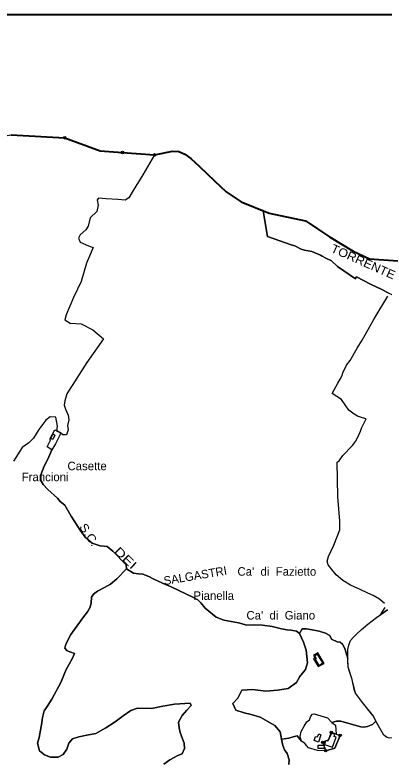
# Model space of a CAD drawing. Extents: x 645880 to 658994, y 884400 to 894744.
# Drawn here: x 656935 to 657672, y 893255 to 894744 of the extents above; entities that cross this region are included whole.
import ezdxf
from ezdxf.enums import TextEntityAlignment as Align

# ---------------------------------------------------------------- set-up
doc = ezdxf.new("R2010")
doc.units = 0
doc.header["$LTSCALE"] = 10
doc.header["$PDMODE"] = 32
doc.header["$PDSIZE"] = 5
for name, color, linetype, lineweight in [('16', 7, 'Continuous', 25), ('17', 7, 'Continuous', 25), ('18', 7, 'Continuous', 25), ('3', 7, 'Continuous', 25), ('4', 7, 'Continuous', 25), ('43', 7, 'Continuous', 25), ('59', 7, 'Continuous', 40), ('62', 7, 'Continuous', 35), ('7', 7, 'Continuous', 25), ('8', 7, 'Continuous', 25)]:
    doc.layers.add(name, color=color, linetype=linetype, lineweight=lineweight)
doc.layers.add('60', color=7, linetype='Continuous')

msp = doc.modelspace()

# ---------------------------------------------------------------- linework, layer by layer
at = {"layer": '16'}
for points in [[(657680.24, 894188.92), (657666.12, 894195.92), (657645.87, 894205.42), (657629.62, 894213.92), (657618.12, 894219.92), (657616.37, 894220.92), (657614.62, 894216.92), (657579.24, 894241.42), (657567.24, 894252.42), (657555.8, 894257.92), (657548.37, 894261.67), (657544.99, 894263.92), (657527.62, 894270.92), (657513.24, 894273.92), (657506.49, 894275.92), (657493.74, 894282.67), (657486.49, 894284.42), (657439.24, 894300.98), (657430.78, 894352.65), (657387.01, 894370.39), (657356.62, 894390.26), (657333.58, 894412.71), (657303.9, 894440.82), (657286.23, 894457.27), (657274.22, 894465.5), (657262.2, 894470.98), (657249.48, 894471.67), (657214.17, 894464.13), (657190.39, 894424.35), (657171.14, 894392.96), (657162.82, 894378.21), (657155.44, 894373.93), (657140.71, 894374.88), (657117.2, 894376.49), (657102.45, 894377.5)], [(657102.45, 894377.5), (657099.36, 894374.4), (657101.73, 894363.47), (657098.63, 894351.34), (657085.32, 894338.26), (657081.52, 894322.08), (657077, 894314.71), (657065.83, 894304.49), (657062.03, 894297.83), (657065.83, 894289.74), (657081.99, 894282.84), (657091.51, 894279.27), (657078.2, 894247.64), (657067.74, 894211.49), (657052.53, 894179.14), (657037.54, 894144.89), (657035.17, 894134.9), (657045.63, 894128.25), (657067.73, 894127.06), (657091.02, 894114.93), (657112.41, 894097.09)], [(657672.88, 893568.11), (657662.51, 893576.7), (657650.21, 893584), (657639.22, 893589.1), (657624.33, 893596.13), (657604.73, 893604.78), (657589.74, 893614.01), (657576.62, 893625.21), (657567.51, 893635.85), (657560.6, 893645.47), (657558.57, 893652.72), (657561.27, 893662.35), (657571.39, 893684.62), (657583.37, 893715.34), (657583.98, 893732.83), (657579.37, 893781.87), (657578.57, 893850.22), (657582.32, 893853.22), (657589.83, 893863.48), (657609.12, 893883.73), (657614.7, 893891.81), (657619.99, 893901.51), (657625.04, 893912.56), (657627.19, 893918.71), (657636.08, 893937.11), (657628.85, 893938.92), (657619.17, 893942.51), (657612.37, 893946.53), (657601.47, 893954.52), (657594.54, 893964.93), (657587.26, 893975.31), (657568.2, 893987.82), (657579.64, 894007.93), (657584.42, 894016.54), (657587.4, 894022.17), (657589.36, 894028.91), (657596.75, 894044.05), (657604.14, 894053.55), (657618.57, 894078.19), (657628.07, 894094.38), (657652.34, 894136.63), (657679.35, 894181.74)], [(657112.41, 894097.09), (657079.13, 894049.76), (657038.73, 893986.97), (657034.69, 893973.18), (657033.5, 893964.62), (657036.12, 893956.05), (657041.82, 893944.4), (657043.07, 893935.18), (657040.6, 893923.66), (657041.42, 893914.88), (657038.13, 893904.74), (657031.28, 893905.28), (657026.77, 893908.54), (657016.62, 893887.42), (657009.04, 893874.78)], [(657019.22, 893912.86), (657020.67, 893922.52), (657017.3, 893940.67), (657006.06, 893941.22), (656997.02, 893934.09), (656983.31, 893915.98), (656972.62, 893898.7), (656963.3, 893888.83), (656949.6, 893879.77), (656932.32, 893852.34)], [(657119.22, 893681.72), (657105.7, 893683.65), (657089.6, 893688.81), (657075.44, 893700.4), (657065.78, 893714.58), (657047.75, 893742.92), (657034.87, 893764.82), (657025.86, 893771.91), (657020.07, 893778.35), (657001.4, 893795.75), (656991.74, 893806.05), (656987.23, 893813.78), (656987.23, 893825.38), (656993.67, 893842.77), (657000.75, 893856.3), (657009.04, 893874.78), (656999.62, 893880.98), (657006.79, 893895.56), (657005.31, 893896.4), (657015.34, 893915.09), (657019.22, 893912.86)], [(657009.04, 893874.78), (657000.75, 893856.3), (656993.67, 893842.77), (656987.23, 893825.38), (656987.23, 893813.78), (656991.74, 893806.05), (657001.4, 893795.75), (657020.07, 893778.35), (657025.86, 893771.91), (657034.87, 893764.82), (657047.75, 893742.92), (657065.78, 893714.58), (657075.44, 893700.4), (657089.6, 893688.81), (657105.7, 893683.65), (657119.22, 893681.72)], [(657119.22, 893681.72), (657130.81, 893672.7), (657157.2, 893645.65), (657157.74, 893637.45), (657171.78, 893628.6), (657181.93, 893627.52), (657190.56, 893627.08), (657202.66, 893622.12), (657212.37, 893616.71), (657229.86, 893608.5), (657247.13, 893601.16), (657291.59, 893580.22), (657300.62, 893575.77), (657306.05, 893569.42), (657314.88, 893558.86), (657337.07, 893540.63), (657352.16, 893535.21), (657381.43, 893529.4), (657398.06, 893525.01), (657413.12, 893525.56), (657429.69, 893524.89), (657448.71, 893522.33), (657467.19, 893517.72), (657478.28, 893515.67), (657486.74, 893515.15), (657497.47, 893512.76), (657503.21, 893508.52), (657508.74, 893517.63)], [(657157.74, 893637.45), (657157.2, 893645.65), (657130.81, 893672.7), (657119.22, 893681.72)], [(657085.41, 893560.96), (657087.57, 893569.39), (657088.22, 893580.63), (657092.32, 893586.89), (657099.87, 893592.94), (657114.35, 893599.86), (657125.79, 893606.77), (657138.74, 893617.14), (657157.74, 893637.45)], [(657284.88, 893368.8), (657253.74, 893367.13), (657230.64, 893363.11), (657208.2, 893358.75), (657179.74, 893359.42), (657166.35, 893354.39), (657151.61, 893343.67), (657135.21, 893331.61), (657117.12, 893319.55), (657097.03, 893308.82), (657078.95, 893305.47), (657063.21, 893302.12), (657050.15, 893298.1), (657043.12, 893289.39), (657039.1, 893276.99), (657031.88, 893266.47), (657021.51, 893261.29), (657006.4, 893261.29), (656994.53, 893266.04), (656984.38, 893273.82), (656980.71, 893288.94), (656983.95, 893300.39), (656989.34, 893330), (656990.2, 893340.58), (656993.87, 893353.76), (656999.7, 893362.19), (657009.2, 893377.09), (657026.91, 893410.58), (657037.7, 893436.08), (657049.36, 893457.47), (657054.54, 893468.49), (657047.2, 893471.3), (657039.64, 893473.67), (657034.89, 893478.86), (657037.04, 893486.86), (657046.98, 893506.09), (657059.07, 893522.72), (657073.1, 893542.38), (657080.44, 893551.46), (657085.41, 893560.96)], [(657664.52, 893545.6), (657669.76, 893553.16), (657674.01, 893559.93)], [(657599.36, 893458.2), (657599.36, 893476.54), (657601.58, 893484.76), (657605.14, 893494.1), (657610.48, 893500.34), (657616.26, 893506.56), (657626.7, 893516.56), (657639.38, 893527.02), (657656.7, 893540.36), (657664.52, 893545.6)], [(657508.74, 893517.63), (657517.02, 893517.63), (657528.61, 893515.7), (657542.14, 893512.94), (657555.39, 893508.79), (657563.39, 893504.1), (657567.26, 893496.91), (657578.3, 893491.39), (657584.09, 893491.11), (657589.06, 893486.69), (657593.76, 893478.41), (657599.36, 893458.2)], [(657232.31, 893247.17), (657244.7, 893256.22), (657260.77, 893264.26), (657268.81, 893267.61), (657273.46, 893278.26), (657272.83, 893289.39), (657269.48, 893298.1), (657265.13, 893310.5), (657263.12, 893319.55), (657261.78, 893330.94), (657269.14, 893344.34), (657278.18, 893355.06), (657286.89, 893364.78), (657284.88, 893368.8)]]:
    msp.add_lwpolyline(points, dxfattribs=at)
at = {"layer": '17'}
for points in [[(657672.88, 893568.11), (657662.51, 893576.7), (657650.21, 893584), (657639.22, 893589.1), (657624.33, 893596.13), (657604.73, 893604.78), (657589.74, 893614.01), (657576.62, 893625.21), (657567.51, 893635.85), (657560.6, 893645.47), (657558.57, 893652.72), (657561.27, 893662.35), (657571.39, 893684.62), (657583.37, 893715.34), (657583.98, 893732.83), (657579.37, 893781.87), (657578.57, 893850.22), (657582.32, 893853.22), (657589.83, 893863.48), (657609.12, 893883.73), (657614.7, 893891.81), (657619.99, 893901.51), (657625.04, 893912.56), (657627.19, 893918.71), (657636.08, 893937.11), (657628.85, 893938.92), (657619.17, 893942.51), (657612.37, 893946.53), (657601.47, 893954.52), (657594.54, 893964.93), (657587.26, 893975.31), (657568.2, 893987.82), (657579.64, 894007.93), (657584.42, 894016.54), (657587.4, 894022.17), (657589.36, 894028.91), (657596.75, 894044.05), (657604.14, 894053.55), (657618.57, 894078.19), (657628.07, 894094.38), (657652.34, 894136.63), (657679.35, 894181.74)], [(657676.92, 893301.52), (657671.6, 893305.52), (657655.6, 893333.1), (657650.7, 893343.1), (657646.7, 893348), (657628.7, 893370.46), (657619.14, 893383.58), (657614.92, 893389.14), (657613.14, 893393.58), (657608.26, 893416.26), (657603.14, 893432.28), (657600.26, 893440.72), (657599.36, 893453.86), (657599.36, 893476.54), (657601.58, 893484.76), (657605.14, 893494.1), (657610.48, 893500.34), (657616.26, 893506.56), (657626.7, 893516.56), (657639.38, 893527.02), (657656.7, 893540.36), (657678.94, 893555.26)], [(657678.94, 893555.26), (657664.52, 893545.6), (657669.76, 893553.16), (657674.01, 893559.93)], [(657563.39, 893504.1), (657555.39, 893508.79), (657542.14, 893512.94), (657528.61, 893515.7), (657517.02, 893517.63), (657508.74, 893517.63), (657503.21, 893508.52), (657511.03, 893491.07), (657516.32, 893474.67), (657518.95, 893449.95), (657515.36, 893436.42), (657503.77, 893422.33), (657497.14, 893410.45), (657480.45, 893398.51), (657459.32, 893394.92), (657436.08, 893393.38), (657409.67, 893396.46), (657388.22, 893395.1), (657380.35, 893379.34), (657369.85, 893368.54), (657375.87, 893354.95), (657392.77, 893349.82), (657407.03, 893346.75), (657424.46, 893341.11), (657454.04, 893324.72), (657464.6, 893311.9), (657467.21, 893296.94)], [(657559.28, 893339.72), (657567.74, 893330.62), (657576.88, 893332.9), (657585.81, 893332.9), (657597.05, 893329.59), (657613.59, 893325.29), (657625.49, 893321.65), (657631.45, 893320.99), (657638.72, 893322.64), (657648.98, 893326.28), (657655.6, 893333.1), (657650.7, 893343.1), (657628.7, 893370.46), (657614.92, 893389.14), (657608.26, 893416.26), (657600.26, 893440.72), (657599.36, 893458.2), (657593.76, 893478.41), (657589.06, 893486.69), (657584.09, 893491.11), (657578.3, 893491.39), (657567.26, 893496.91), (657563.39, 893504.1)], [(657467.21, 893296.94), (657472.69, 893298.15), (657481.78, 893299.45), (657490.22, 893302.12), (657498.49, 893303.78), (657507.3, 893292.99), (657505.1, 893298.91), (657504.64, 893303.47), (657506.44, 893312.49), (657512.32, 893323.08), (657518.1, 893331.9), (657522.83, 893335.49), (657525.88, 893343.32), (657528.94, 893347.47), (657532.36, 893347.54), (657559.28, 893339.72)], [(657655.6, 893333.1), (657648.98, 893326.28), (657638.72, 893322.64), (657631.45, 893320.99), (657625.49, 893321.65), (657613.59, 893325.29), (657597.05, 893329.59), (657585.81, 893332.9), (657576.88, 893332.9), (657567.74, 893330.62), (657574.83, 893325.04), (657576.28, 893307.44), (657584.17, 893304.83), (657573.38, 893279.22), (657555.55, 893274.18)], [(657732.7, 893315.98), (657729.16, 893316.2), (657724.48, 893316.2), (657718.92, 893313.98), (657692.26, 893300.2), (657688.04, 893299.52), (657680.92, 893299.74), (657676.92, 893301.52), (657671.6, 893305.52), (657655.6, 893333.1)], [(657507.3, 893292.99), (657498.49, 893303.78), (657490.22, 893302.12), (657481.78, 893299.45), (657472.69, 893298.15), (657467.21, 893296.94)], [(657467.21, 893296.94), (657469.85, 893284.3), (657473.55, 893275.59), (657478.31, 893268.42), (657482.36, 893255.7), (657482.12, 893246.39)], [(657521.37, 893279.84), (657513.64, 893288.51), (657507.3, 893292.99)], [(657555.55, 893274.18), (657538.97, 893274.76), (657521.37, 893279.84)]]:
    msp.add_lwpolyline(points, dxfattribs=at)
msp.add_point((657555.55, 893274.18), dxfattribs=at)
at = {"layer": '18'}
for points in [[(656861.31, 894493.63), (656927.73, 894504.6), (656981.21, 894501.51), (657034.69, 894498.43)], [(657034.69, 894498.43), (657105.36, 894472.38), (657127.62, 894470.67), (657149.88, 894468.95)], [(657214.18, 894464.16), (657190.39, 894424.35), (657171.14, 894392.96), (657162.82, 894378.21), (657155.44, 894373.93), (657140.71, 894374.88), (657117.2, 894376.49), (657102.45, 894377.5)], [(657149.88, 894468.95), (657182.03, 894466.55), (657214.18, 894464.16)], [(657102.45, 894377.5), (657099.36, 894374.4), (657101.73, 894363.47), (657098.63, 894351.34), (657085.32, 894338.26), (657081.52, 894322.08), (657077, 894314.71), (657065.83, 894304.49), (657062.03, 894297.83), (657065.83, 894289.74), (657081.99, 894282.84), (657091.51, 894279.27), (657078.2, 894247.64), (657067.74, 894211.49), (657052.53, 894179.14), (657037.54, 894144.89), (657035.17, 894134.9), (657045.63, 894128.25), (657067.73, 894127.06), (657091.02, 894114.93), (657112.41, 894097.09)], [(657112.41, 894097.09), (657079.13, 894049.76), (657038.73, 893986.97), (657034.69, 893973.18), (657033.5, 893964.62), (657036.12, 893956.05), (657041.82, 893944.4), (657043.07, 893935.18), (657040.6, 893923.66), (657041.42, 893914.88), (657038.13, 893904.74), (657031.28, 893905.28), (657026.77, 893908.54)], [(657026.77, 893908.54), (657019.22, 893912.86), (657020.67, 893922.52), (657017.3, 893940.67), (657006.06, 893941.22), (656997.02, 893934.09), (656983.31, 893915.98), (656972.62, 893898.7), (656963.3, 893888.83), (656949.6, 893879.77), (656932.32, 893852.34)], [(657497.47, 893512.76), (657486.74, 893515.15), (657478.28, 893515.67), (657467.19, 893517.72), (657448.71, 893522.33), (657429.69, 893524.89), (657413.12, 893525.56), (657398.06, 893525.01), (657381.43, 893529.4), (657352.16, 893535.21), (657337.07, 893540.63), (657314.88, 893558.86), (657306.05, 893569.42), (657300.62, 893575.77), (657291.59, 893580.22), (657247.13, 893601.16), (657229.86, 893608.5), (657212.37, 893616.71), (657202.66, 893622.12), (657190.56, 893627.08), (657181.93, 893627.52), (657171.78, 893628.6), (657157.74, 893637.45), (657138.74, 893617.14), (657125.79, 893606.77), (657114.35, 893599.86), (657099.87, 893592.94), (657092.32, 893586.89), (657088.22, 893580.63), (657087.57, 893569.39), (657085.41, 893560.96), (657080.44, 893551.46)], [(657080.44, 893551.46), (657073.1, 893542.38), (657059.07, 893522.72), (657046.98, 893506.09), (657037.04, 893486.86), (657034.89, 893478.86), (657039.64, 893473.67), (657047.2, 893471.3), (657054.54, 893468.49), (657049.36, 893457.47), (657037.7, 893436.08), (657026.91, 893410.58), (657009.2, 893377.09), (656999.7, 893362.19), (656993.87, 893353.76), (656990.2, 893340.58), (656989.34, 893330), (656983.95, 893300.39), (656980.71, 893288.94), (656984.38, 893273.82), (656994.53, 893266.04), (657006.4, 893261.29), (657021.51, 893261.29), (657031.88, 893266.47), (657039.1, 893276.99), (657043.12, 893289.39), (657050.15, 893298.1), (657063.21, 893302.12), (657078.95, 893305.47), (657097.03, 893308.82), (657117.12, 893319.55), (657135.21, 893331.61), (657151.61, 893343.67), (657166.35, 893354.39), (657179.74, 893359.42), (657208.2, 893358.75), (657230.64, 893363.11), (657253.74, 893367.13), (657284.88, 893368.8), (657286.89, 893364.78)], [(657482.12, 893246.4), (657482.36, 893255.7), (657478.31, 893268.42), (657473.55, 893275.59), (657469.85, 893284.3), (657467.21, 893296.95), (657464.6, 893311.9), (657454.04, 893324.72), (657424.46, 893341.11), (657407.03, 893346.75), (657392.77, 893349.82), (657375.87, 893354.95), (657369.85, 893368.54), (657380.35, 893379.34), (657388.22, 893395.1), (657409.67, 893396.46), (657436.08, 893393.38), (657459.32, 893394.92), (657480.45, 893398.51), (657497.14, 893410.45), (657503.76, 893422.33), (657515.36, 893436.42), (657518.95, 893449.96), (657516.32, 893474.67), (657511.03, 893491.07), (657503.21, 893508.52), (657497.47, 893512.76)], [(657286.89, 893364.78), (657278.18, 893355.06), (657269.14, 893344.34), (657261.78, 893330.94), (657263.12, 893319.55), (657265.13, 893310.5), (657269.48, 893298.1), (657272.83, 893289.39), (657273.46, 893278.26), (657268.81, 893267.61), (657260.77, 893264.26), (657244.7, 893256.22), (657232.31, 893247.17)]]:
    msp.add_lwpolyline(points, dxfattribs=at)
for p in [(657034.69, 894498.43), (657149.88, 894468.95), (657214.18, 894464.16)]:
    msp.add_point(p, dxfattribs=at)
at = {"layer": '3'}
msp.add_line((657549.3, 893291.02), (657555.55, 893274.18), dxfattribs=at)
for points in [[(657534.79, 893302.59), (657539.12, 893301.81), (657541.67, 893307.96), (657546.05, 893305.88), (657540.99, 893291.44), (657532.4, 893294.31)], [(657555.28, 893293.79), (657553.18, 893286.88), (657569.32, 893280.96), (657576.21, 893301.24), (657572.16, 893302.86), (657573.92, 893306.51), (657567.04, 893309.37), (657559.98, 893292.93)], [(657540.52, 893285.39), (657552.2, 893285.47), (657552.24, 893278.86), (657540.69, 893278.8)]]:
    msp.add_lwpolyline(points, close=True, dxfattribs=at)
for points in [[(657566.55, 893310.49), (657560.49, 893295.16), (657549.3, 893291.02)], [(657555.55, 893274.18), (657573.38, 893279.22), (657584.17, 893304.83)]]:
    msp.add_lwpolyline(points, dxfattribs=at)
for p in [(657566.55, 893310.49), (657584.17, 893304.83), (657549.3, 893291.02)]:
    msp.add_point(p, dxfattribs=at)
at = {"layer": '4'}
for points in [[(657015.34, 893915.09), (657026.77, 893908.54), (657016.62, 893887.42), (657009.04, 893874.78), (656999.62, 893880.98), (657006.79, 893895.56), (657005.31, 893896.4)], [(657011.56, 893906.97), (657015.37, 893904.22), (657010.92, 893895.74), (657006.9, 893897.86)], [(657531.34, 893457.37), (657540.48, 893442.31), (657552.08, 893448.51), (657539.64, 893469.64), (657531.26, 893464.75), (657533.75, 893459.39)]]:
    msp.add_lwpolyline(points, close=True, dxfattribs=at)
at = {"layer": '43'}
for points in [[(657699.64, 894252.51), (657643.11, 894256.63), (657610.31, 894271.68), (657562.97, 894300.47), (657527.09, 894325.23), (657514.91, 894332.68), (657442.84, 894347.77), (657430.74, 894352.91), (657439.24, 894300.98), (657486.49, 894284.42), (657493.74, 894282.67), (657506.49, 894275.92), (657513.24, 894273.92), (657527.62, 894270.92), (657544.99, 894263.92), (657548.37, 894261.67), (657555.8, 894257.92), (657567.24, 894252.42), (657579.24, 894241.42), (657614.62, 894216.92), (657616.37, 894220.92)], [(657616.37, 894220.92), (657618.12, 894219.92), (657629.62, 894213.92), (657645.87, 894205.42), (657666.12, 894195.92), (657680.24, 894188.92), (657697.12, 894180.42), (657706.24, 894176.42), (657709.24, 894175.92), (657711.62, 894175.92)]]:
    msp.add_lwpolyline(points, dxfattribs=at)
at = {"layer": '59'}
for points in [[(656927.7, 894504.57), (657034.66, 894498.4), (657105.33, 894472.35), (657149.85, 894468.92), (657214.15, 894464.13), (657249.48, 894471.67), (657262.2, 894470.98), (657274.22, 894465.5)], [(657274.22, 894465.5), (657286.23, 894457.27), (657303.9, 894440.82), (657333.58, 894412.71), (657356.62, 894390.26), (657387.01, 894370.39), (657442.84, 894347.77), (657514.91, 894332.68), (657562.97, 894300.47), (657610.31, 894271.68), (657643.11, 894256.63), (657699.64, 894252.51)]]:
    msp.add_lwpolyline(points, dxfattribs=at)
at = {"layer": '62', "lineweight": 40}
msp.add_lwpolyline([(650022.35, 889003.81), (658994.16, 889003.81), (658994.16, 894743.81), (650022.35, 894743.81)], close=True, dxfattribs=at)
msp.add_lwpolyline([(650022.35, 889003.81), (658994.16, 889003.81), (658994.16, 894743.81), (650022.35, 894743.81)], close=True, dxfattribs=at)
at = {"layer": '7'}
msp.add_lwpolyline([(657534.37, 893457.21), (657541.8, 893444.62), (657549.89, 893449.95), (657539.02, 893466.84), (657533.65, 893463.5), (657536.23, 893458.46)], close=True, dxfattribs=at)
at = {"layer": '8'}
msp.add_lwpolyline([(657532.36, 893347.54), (657559.28, 893339.72), (657567.74, 893330.62), (657574.83, 893325.04), (657576.28, 893307.44), (657566.55, 893310.49), (657560.49, 893295.16), (657549.3, 893291.02), (657555.55, 893274.18), (657538.97, 893274.76), (657521.37, 893279.84), (657513.64, 893288.51), (657507.3, 893292.99), (657505.1, 893298.91), (657504.64, 893303.47), (657506.44, 893312.49), (657512.32, 893323.08), (657518.1, 893331.9), (657522.83, 893335.49), (657525.88, 893343.32), (657528.94, 893347.47)], close=True, dxfattribs=at)

# ---------------------------------------------------------------- texts
at = {"layer": '60'}
for s, rotation, width, p in [('TORRENTE ', 336.023, 1.1, (657630.12, 894241.78)), ('S.C.', 303.489, 1.1, (657076.26, 893700.84)), ('DEI', 315.862, 1.35, (657150.36, 893653.04))]:
    msp.add_text(s, height=17, rotation=rotation, dxfattribs=dict(at, width=width)).set_placement(p, align=Align.CENTER)
for s, p in [('Casette', (657079.39, 893834.39)), ('Francioni', (656995.68, 893812.48)), ("Ca'  di  Fazietto", (657457.99, 893623.67)), ('Pianella', (657332.1, 893575.46)), ("Ca'  di  Giano", (657465.86, 893536.18))]:
    msp.add_text(s, height=17, dxfattribs=at).set_placement(p, align=Align.CENTER)
msp.add_text('SALGASTRI', height=17, rotation=9.557, dxfattribs=at).set_placement((657296.49, 893615.38), align=Align.CENTER)

doc.saveas('drawing.dxf')
